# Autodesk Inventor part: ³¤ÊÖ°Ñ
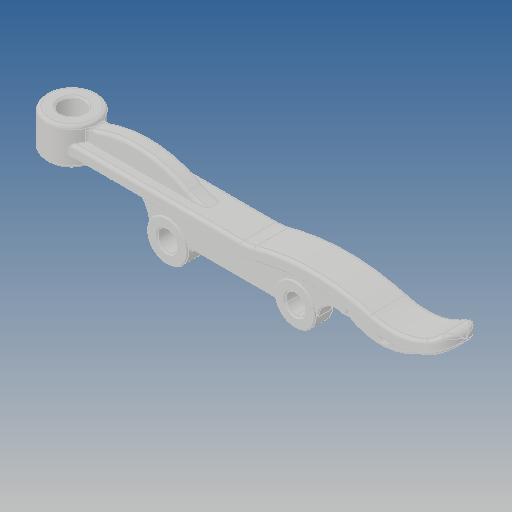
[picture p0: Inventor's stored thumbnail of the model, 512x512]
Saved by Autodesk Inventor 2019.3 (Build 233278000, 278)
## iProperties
Created: 2017-12
Part Number: ³¤ÊÖ°Ñ
Material: Ogólny
Document SubType Name: Modeling
Designer: Admin
Density: 1 g/cm^3
Appearance: Domyślna
Author: Admin
Revision Number: ÈÎºÎ
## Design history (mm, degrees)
feature "Ô²½Ç34"
node "Bryła1"
